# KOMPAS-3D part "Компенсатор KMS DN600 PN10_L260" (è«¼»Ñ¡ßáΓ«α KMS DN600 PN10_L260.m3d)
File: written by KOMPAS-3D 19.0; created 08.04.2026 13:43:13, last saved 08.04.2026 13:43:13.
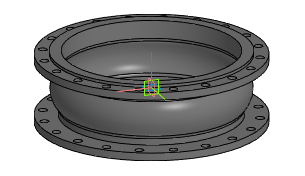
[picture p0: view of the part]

Document properties: Автор: Энергия; Полное имя файла: Z:\3.Личные\kachalov\3d для проектировщиков\7.1 Компенсатор\stp_Компенсатор KSM\Компенсатор KMS DN600 PN10_L260.m3d

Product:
- Part/product: Компенсатор KMS DN600 PN10_L260

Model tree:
1. Операция без истории:1  (labels: Компенсатор KMS DN600 PN10_L260)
